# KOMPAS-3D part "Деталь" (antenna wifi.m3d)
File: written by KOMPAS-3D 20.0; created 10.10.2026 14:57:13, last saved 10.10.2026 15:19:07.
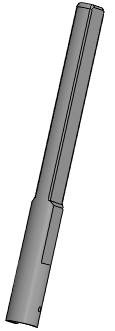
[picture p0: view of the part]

Document properties: Полное имя файла: D:\myProjects\Progect_esp32\box_compas\antenna wifi.m3d

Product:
- Part/product: Деталь
    Масса: 0.0941381

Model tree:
1. Эскиз:1
2. Элемент выдавливания:1
     Расстояние 1 = 130
3. Смещенная плоскость:1
     Расстояние = 10
4. Эскиз:2  (with: Элемент выдавливания:1)
5. Элемент выдавливания:3
     Расстояние 2 = 16.5
6. Скругление:1  (with: Элемент выдавливания:1)
     Радиус = 2
7. Скругление:2  (with: Элемент выдавливания:3)
     Радиус = 1
8. Скругление:3  (with: Элемент выдавливания:3)
     Радиус = 1
9. Фаска:1  (with: Элемент выдавливания:3)
     Угол = 45; Длина 1 = 1.5; Длина 2 = 1.5
10. Эскиз:3  (with: Элемент выдавливания:1)
11. Эскиз:4  (with: Элемент выдавливания:1)
12. Элемент выдавливания:4
     Расстояние 2 = 12
13. Элемент выдавливания:5
     Расстояние 2 = 10
14. Скругление:4  (with: Элемент выдавливания:5)
     Радиус = 1
15. Смещенная плоскость:2
     Расстояние = 10
16. Эскиз:5  (with: Элемент выдавливания:1)
17. Элемент выдавливания:6
     Расстояние 2 = 16.5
